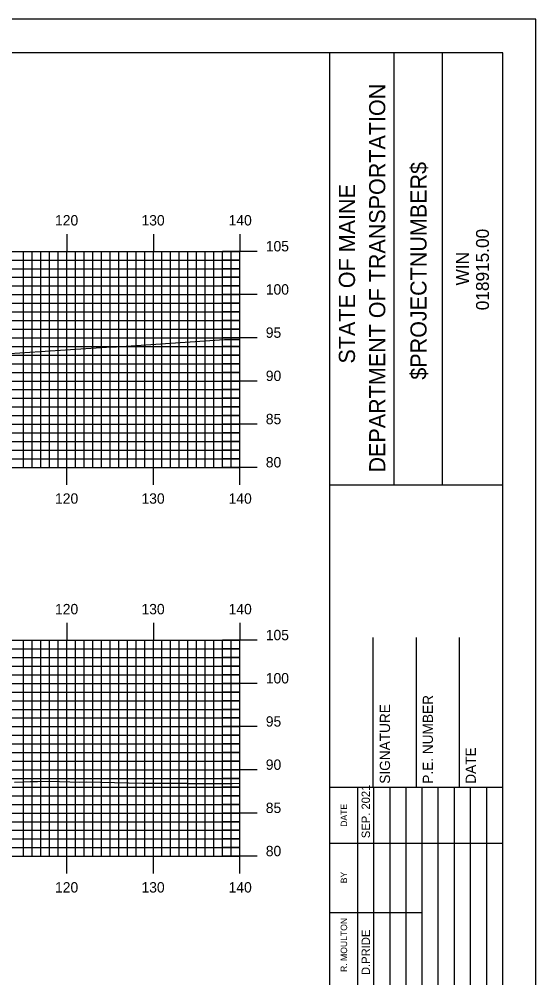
# Model space of a CAD drawing. Extents: x 1763365 to 1763708, y 442591 to 442811.
# Drawn here: x 1763645.3 to 1763705, y 442699.6 to 442810.5 of the extents above; entities that cross this region are included whole.
import ezdxf

# ---------------------------------------------------------------- set-up
doc = ezdxf.new("R2010")
doc.units = 0
for name, color, linetype in [('BORDER', 7, 'Continuous'), ('H_V ANNOTATION', 7, 'Continuous'), ('MAJOR', 7, 'Continuous'), ('MINOR', 7, 'Continuous'), ('PLOT BOUNDARY', 7, 'Continuous'), ('S_Roadway_Centerline', 7, 'Continuous')]:
    doc.layers.add(name, color=color, linetype=linetype)

msp = doc.modelspace()

# ---------------------------------------------------------------- linework, layer by layer
at = {"layer": 'BORDER'}
for p, q in [((1763681.21, 442596.67), (1763681.21, 442806.67)), ((1763688.66, 442756.66), (1763688.66, 442806.66)), ((1763694.25, 442756.66), (1763694.25, 442806.66)), ((1763681.21, 442756.65), (1763701.21, 442756.65)), ((1763686.21, 442721.67), (1763686.21, 442738.97)), ((1763691.21, 442721.67), (1763691.21, 442738.97)), ((1763696.21, 442721.67), (1763696.21, 442738.97)), ((1763681.21, 442721.67), (1763701.21, 442721.67))]:
    msp.add_line(p, q, dxfattribs=at)
msp.add_lwpolyline([(1763381.21, 442596.67), (1763701.21, 442596.67), (1763701.21, 442806.67), (1763381.21, 442806.67)], close=True, dxfattribs=at)
for points in [[(1763684.44, 442715.17), (1763684.44, 442721.67)], [(1763686.3, 442686.68), (1763686.3, 442721.67)], [(1763688.16, 442721.67), (1763688.16, 442686.68)], [(1763690.03, 442686.68), (1763690.03, 442721.67)], [(1763691.89, 442686.68), (1763691.89, 442721.67)], [(1763693.75, 442686.68), (1763693.75, 442721.67)], [(1763695.62, 442686.68), (1763695.62, 442721.67)], [(1763697.48, 442686.68), (1763697.48, 442721.67)], [(1763699.34, 442686.68), (1763699.34, 442721.67)], [(1763684.44, 442686.68), (1763684.44, 442720.26)], [(1763681.21, 442715.17), (1763701.21, 442715.17)], [(1763681.21, 442707.17), (1763684.44, 442707.17)], [(1763684.44, 442707.17), (1763691.89, 442707.17)]]:
    msp.add_lwpolyline(points, dxfattribs=at)
at = {"layer": 'MAJOR'}
for p, q in [((1763650.81, 442785.67), (1763650.81, 442783.67)), ((1763660.81, 442785.67), (1763660.81, 442783.67)), ((1763670.81, 442785.67), (1763670.81, 442783.67)), ((1763390.81, 442783.67), (1763670.81, 442783.67)), ((1763390.81, 442783.67), (1763670.81, 442783.67)), ((1763650.81, 442758.67), (1763650.81, 442783.67)), ((1763660.81, 442758.67), (1763660.81, 442783.67)), ((1763672.81, 442783.67), (1763668.8, 442783.67)), ((1763670.81, 442758.67), (1763670.81, 442783.67)), ((1763670.81, 442758.67), (1763670.81, 442783.67)), ((1763390.81, 442778.67), (1763670.81, 442778.67)), ((1763672.81, 442778.67), (1763668.8, 442778.67)), ((1763390.81, 442773.67), (1763670.81, 442773.67)), ((1763672.81, 442773.67), (1763668.8, 442773.67)), ((1763390.81, 442768.67), (1763670.81, 442768.67)), ((1763672.81, 442768.67), (1763668.8, 442768.67)), ((1763390.81, 442763.67), (1763670.81, 442763.67)), ((1763672.81, 442763.67), (1763668.8, 442763.67)), ((1763390.81, 442758.67), (1763670.81, 442758.67)), ((1763390.81, 442758.67), (1763670.81, 442758.67)), ((1763650.81, 442756.66), (1763650.81, 442758.67)), ((1763660.81, 442756.66), (1763660.81, 442758.67)), ((1763672.81, 442758.67), (1763668.8, 442758.67)), ((1763670.81, 442756.66), (1763670.81, 442758.67)), ((1763650.81, 442740.67), (1763650.81, 442738.67)), ((1763660.81, 442740.67), (1763660.81, 442738.67)), ((1763670.81, 442740.67), (1763670.81, 442738.67)), ((1763390.81, 442738.67), (1763670.81, 442738.67)), ((1763390.81, 442738.67), (1763670.81, 442738.67)), ((1763650.81, 442713.67), (1763650.81, 442738.67)), ((1763660.81, 442713.67), (1763660.81, 442738.67)), ((1763672.81, 442738.67), (1763668.8, 442738.67)), ((1763670.81, 442713.67), (1763670.81, 442738.67)), ((1763670.81, 442713.67), (1763670.81, 442738.67)), ((1763390.81, 442733.67), (1763670.81, 442733.67)), ((1763672.81, 442733.67), (1763668.8, 442733.67)), ((1763390.81, 442728.67), (1763670.81, 442728.67)), ((1763672.81, 442728.67), (1763668.8, 442728.67)), ((1763390.81, 442723.67), (1763670.81, 442723.67)), ((1763672.81, 442723.67), (1763668.8, 442723.67)), ((1763390.81, 442718.67), (1763670.81, 442718.67)), ((1763672.81, 442718.67), (1763668.8, 442718.67)), ((1763390.81, 442713.67), (1763670.81, 442713.67)), ((1763390.81, 442713.67), (1763670.81, 442713.67)), ((1763650.81, 442711.66), (1763650.81, 442713.67)), ((1763660.81, 442711.66), (1763660.81, 442713.67)), ((1763672.81, 442713.67), (1763668.8, 442713.67)), ((1763670.81, 442711.66), (1763670.81, 442713.67))]:
    msp.add_line(p, q, dxfattribs=at)
at = {"layer": 'MINOR'}
for p, q in [((1763645.81, 442758.67), (1763645.81, 442783.67)), ((1763646.81, 442758.67), (1763646.81, 442783.67)), ((1763647.81, 442758.67), (1763647.81, 442783.67)), ((1763648.81, 442758.67), (1763648.81, 442783.67)), ((1763649.81, 442758.67), (1763649.81, 442783.67)), ((1763651.81, 442758.67), (1763651.81, 442783.67)), ((1763652.81, 442758.67), (1763652.81, 442783.67)), ((1763653.81, 442758.67), (1763653.81, 442783.67)), ((1763654.81, 442758.67), (1763654.81, 442783.67)), ((1763655.81, 442758.67), (1763655.81, 442783.67)), ((1763656.81, 442758.67), (1763656.81, 442783.67)), ((1763657.81, 442758.67), (1763657.81, 442783.67)), ((1763658.81, 442758.67), (1763658.81, 442783.67)), ((1763659.81, 442758.67), (1763659.81, 442783.67)), ((1763661.81, 442758.67), (1763661.81, 442783.67)), ((1763662.81, 442758.67), (1763662.81, 442783.67)), ((1763663.81, 442758.67), (1763663.81, 442783.67)), ((1763664.81, 442758.67), (1763664.81, 442783.67)), ((1763665.81, 442758.67), (1763665.81, 442783.67)), ((1763666.81, 442758.67), (1763666.81, 442783.67)), ((1763667.81, 442758.67), (1763667.81, 442783.67)), ((1763668.81, 442758.67), (1763668.81, 442783.67)), ((1763669.81, 442758.67), (1763669.81, 442783.67)), ((1763390.81, 442782.67), (1763670.81, 442782.67)), ((1763390.81, 442781.67), (1763670.81, 442781.67)), ((1763670.81, 442782.67), (1763668.8, 442782.67)), ((1763670.81, 442781.67), (1763668.8, 442781.67)), ((1763390.81, 442780.67), (1763670.81, 442780.67)), ((1763670.81, 442780.67), (1763668.8, 442780.67)), ((1763390.81, 442779.67), (1763670.81, 442779.67)), ((1763670.81, 442779.67), (1763668.8, 442779.67)), ((1763390.81, 442777.67), (1763670.81, 442777.67)), ((1763670.81, 442777.67), (1763668.8, 442777.67)), ((1763390.81, 442776.67), (1763670.81, 442776.67)), ((1763670.81, 442776.67), (1763668.8, 442776.67)), ((1763390.81, 442775.67), (1763670.81, 442775.67)), ((1763670.81, 442775.67), (1763668.8, 442775.67)), ((1763390.81, 442774.67), (1763670.81, 442774.67)), ((1763670.81, 442774.67), (1763668.8, 442774.67)), ((1763390.81, 442772.67), (1763670.81, 442772.67)), ((1763670.81, 442772.67), (1763668.8, 442772.67)), ((1763390.81, 442771.67), (1763670.81, 442771.67)), ((1763390.81, 442770.67), (1763670.81, 442770.67)), ((1763670.81, 442771.67), (1763668.8, 442771.67)), ((1763670.81, 442770.67), (1763668.8, 442770.67)), ((1763390.81, 442769.67), (1763670.81, 442769.67)), ((1763670.81, 442769.67), (1763668.8, 442769.67)), ((1763390.81, 442767.67), (1763670.81, 442767.67)), ((1763670.81, 442767.67), (1763668.8, 442767.67)), ((1763390.81, 442766.67), (1763670.81, 442766.67)), ((1763670.81, 442766.67), (1763668.8, 442766.67)), ((1763390.81, 442765.67), (1763670.81, 442765.67)), ((1763670.81, 442765.67), (1763668.8, 442765.67)), ((1763390.81, 442764.67), (1763670.81, 442764.67)), ((1763670.81, 442764.67), (1763668.8, 442764.67)), ((1763390.81, 442762.67), (1763670.81, 442762.67)), ((1763670.81, 442762.67), (1763668.8, 442762.67)), ((1763390.81, 442761.67), (1763670.81, 442761.67)), ((1763390.81, 442760.67), (1763670.81, 442760.67)), ((1763670.81, 442761.67), (1763668.8, 442761.67)), ((1763670.81, 442760.67), (1763668.8, 442760.67)), ((1763390.81, 442759.67), (1763670.81, 442759.67)), ((1763670.81, 442759.67), (1763668.8, 442759.67)), ((1763645.81, 442713.67), (1763645.81, 442738.67)), ((1763646.81, 442713.67), (1763646.81, 442738.67)), ((1763647.81, 442713.67), (1763647.81, 442738.67)), ((1763648.81, 442713.67), (1763648.81, 442738.67)), ((1763649.81, 442713.67), (1763649.81, 442738.67)), ((1763651.81, 442713.67), (1763651.81, 442738.67)), ((1763652.81, 442713.67), (1763652.81, 442738.67)), ((1763653.81, 442713.67), (1763653.81, 442738.67)), ((1763654.81, 442713.67), (1763654.81, 442738.67)), ((1763655.81, 442713.67), (1763655.81, 442738.67)), ((1763656.81, 442713.67), (1763656.81, 442738.67)), ((1763657.81, 442713.67), (1763657.81, 442738.67)), ((1763658.81, 442713.67), (1763658.81, 442738.67)), ((1763659.81, 442713.67), (1763659.81, 442738.67)), ((1763661.81, 442713.67), (1763661.81, 442738.67)), ((1763662.81, 442713.67), (1763662.81, 442738.67)), ((1763663.81, 442713.67), (1763663.81, 442738.67)), ((1763664.81, 442713.67), (1763664.81, 442738.67)), ((1763665.81, 442713.67), (1763665.81, 442738.67)), ((1763666.81, 442713.67), (1763666.81, 442738.67)), ((1763667.81, 442713.67), (1763667.81, 442738.67)), ((1763668.81, 442713.67), (1763668.81, 442738.67)), ((1763669.81, 442713.67), (1763669.81, 442738.67)), ((1763390.81, 442737.67), (1763670.81, 442737.67)), ((1763670.81, 442737.67), (1763668.8, 442737.67)), ((1763390.81, 442736.67), (1763670.81, 442736.67)), ((1763670.81, 442736.67), (1763668.8, 442736.67)), ((1763390.81, 442735.67), (1763670.81, 442735.67)), ((1763670.81, 442735.67), (1763668.8, 442735.67)), ((1763390.81, 442734.67), (1763670.81, 442734.67)), ((1763670.81, 442734.67), (1763668.8, 442734.67)), ((1763390.81, 442732.67), (1763670.81, 442732.67)), ((1763670.81, 442732.67), (1763668.8, 442732.67)), ((1763390.81, 442731.67), (1763670.81, 442731.67)), ((1763390.81, 442730.67), (1763670.81, 442730.67)), ((1763670.81, 442731.67), (1763668.8, 442731.67)), ((1763670.81, 442730.67), (1763668.8, 442730.67)), ((1763390.81, 442729.67), (1763670.81, 442729.67)), ((1763670.81, 442729.67), (1763668.8, 442729.67)), ((1763390.81, 442727.67), (1763670.81, 442727.67)), ((1763670.81, 442727.67), (1763668.8, 442727.67)), ((1763390.81, 442726.67), (1763670.81, 442726.67)), ((1763670.81, 442726.67), (1763668.8, 442726.67)), ((1763390.81, 442725.67), (1763670.81, 442725.67)), ((1763670.81, 442725.67), (1763668.8, 442725.67)), ((1763390.81, 442724.67), (1763670.81, 442724.67)), ((1763670.81, 442724.67), (1763668.8, 442724.67)), ((1763390.81, 442722.67), (1763670.81, 442722.67)), ((1763670.81, 442722.67), (1763668.8, 442722.67)), ((1763390.81, 442721.67), (1763670.81, 442721.67)), ((1763390.81, 442720.67), (1763670.81, 442720.67)), ((1763390.81, 442720.67), (1763670.81, 442720.67)), ((1763670.81, 442721.67), (1763668.8, 442721.67)), ((1763670.81, 442720.67), (1763668.8, 442720.67)), ((1763390.81, 442719.67), (1763670.81, 442719.67)), ((1763670.81, 442719.67), (1763668.8, 442719.67)), ((1763390.81, 442717.67), (1763670.81, 442717.67)), ((1763670.81, 442717.67), (1763668.8, 442717.67)), ((1763390.81, 442716.67), (1763670.81, 442716.67)), ((1763670.81, 442716.67), (1763668.8, 442716.67)), ((1763390.81, 442715.67), (1763670.81, 442715.67)), ((1763670.81, 442715.67), (1763668.8, 442715.67)), ((1763390.81, 442714.67), (1763670.81, 442714.67)), ((1763670.81, 442714.67), (1763668.8, 442714.67))]:
    msp.add_line(p, q, dxfattribs=at)
at = {"layer": 'PLOT BOUNDARY'}
msp.add_lwpolyline([(1763365.02, 442590.55), (1763705.02, 442590.55), (1763705.02, 442810.55), (1763365.02, 442810.55)], close=True, dxfattribs=at)
at = {"layer": 'S_Roadway_Centerline'}
for points in [[(1763572.5, 442766.97), (1763585.61, 442768.27), (1763594.17, 442769.13), (1763603.7, 442769.25), (1763607.27, 442769.51), (1763614.3, 442769.96), (1763621.41, 442770.44), (1763627.3, 442770.86), (1763638.86, 442771.49), (1763653.01, 442772.44), (1763655.41, 442772.58), (1763656.54, 442772.62), (1763669.02, 442773.47), (1763670.81, 442773.48)], [(1763644.77, 442722.24), (1763645.73, 442722.27), (1763646.62, 442722.3), (1763647.44, 442722.33), (1763648.82, 442722.37), (1763652.31, 442722.25), (1763653.08, 442722.27), (1763659.57, 442722.13), (1763660.71, 442722.13), (1763661.25, 442722.14), (1763661.76, 442722.14), (1763662.24, 442722.14), (1763662.68, 442722.14), (1763663.08, 442722.14), (1763663.44, 442722.14), (1763664.75, 442722.11), (1763664.84, 442722.1), (1763664.93, 442722.1), (1763664.97, 442722.1), (1763665.06, 442722.09), (1763665.27, 442722.08), (1763665.37, 442722.08), (1763665.43, 442722.08), (1763665.47, 442722.08), (1763665.56, 442722.07), (1763665.67, 442722.07), (1763665.78, 442722.07), (1763666.05, 442722.07), (1763666.2, 442722.07), (1763666.36, 442722.07), (1763666.54, 442722.08), (1763666.71, 442722.08), (1763666.89, 442722.08), (1763667.06, 442722.08), (1763667.31, 442722.08), (1763667.61, 442722.08), (1763667.94, 442722.09), (1763668.29, 442722.09), (1763668.64, 442722.09), (1763668.98, 442722.09), (1763669.29, 442722.1), (1763669.55, 442722.1), (1763669.94, 442722.1), (1763670.81, 442722.13)]]:
    msp.add_lwpolyline(points, dxfattribs=at)

# ---------------------------------------------------------------- texts
at = {"layer": 'BORDER'}
for s, height, p in [('DEPARTMENT OF TRANSPORTATION', 1.8635, (1763687.62, 442758.08)), ('$PROJECTNUMBER$', 1.8635, (1763692.39, 442768.82)), ('STATE OF MAINE', 1.8635, (1763684.12, 442770.69)), ('018915.00', 1.491, (1763699.6, 442776.86)), ('WIN', 1.491, (1763697.28, 442779.73)), ('P.E. NUMBER', 1.1811, (1763693.13, 442722.06)), ('SIGNATURE', 1.181, (1763688.17, 442722.06)), ('DATE', 1.181, (1763698.09, 442722.06)), ('SEP. 2021', 0.969, (1763685.85, 442715.76)), ('DATE', 0.743, (1763683.21, 442717.08)), ('BY', 0.743, (1763683.21, 442710.54)), ('R. MOULTON', 0.745, (1763683.21, 442700.28)), ('D.PRIDE', 0.969, (1763685.85, 442699.92))]:
    msp.add_text(s, height=height, rotation=90, dxfattribs=at).set_placement(p)
at = {"layer": 'H_V ANNOTATION'}
for s, p in [('120', (1763649.45, 442786.67)), ('130', (1763659.44, 442786.67)), ('140', (1763669.51, 442786.67)), ('105', (1763673.81, 442783.67)), ('100', (1763673.81, 442778.67)), ('95', (1763673.81, 442773.67)), ('90', (1763673.81, 442768.67)), ('85', (1763673.81, 442763.67)), ('80', (1763673.81, 442758.67)), ('120', (1763649.45, 442754.47)), ('130', (1763659.44, 442754.47)), ('140', (1763669.51, 442754.47)), ('120', (1763649.45, 442741.67)), ('130', (1763659.44, 442741.67)), ('140', (1763669.51, 442741.67)), ('105', (1763673.81, 442738.67)), ('100', (1763673.81, 442733.67)), ('95', (1763673.81, 442728.67)), ('90', (1763673.81, 442723.67)), ('85', (1763673.81, 442718.67)), ('80', (1763673.81, 442713.67)), ('120', (1763649.45, 442709.47)), ('130', (1763659.44, 442709.47)), ('140', (1763669.51, 442709.47))]:
    msp.add_text(s, height=1.2, dxfattribs=at).set_placement(p)

doc.saveas('drawing.dxf')
